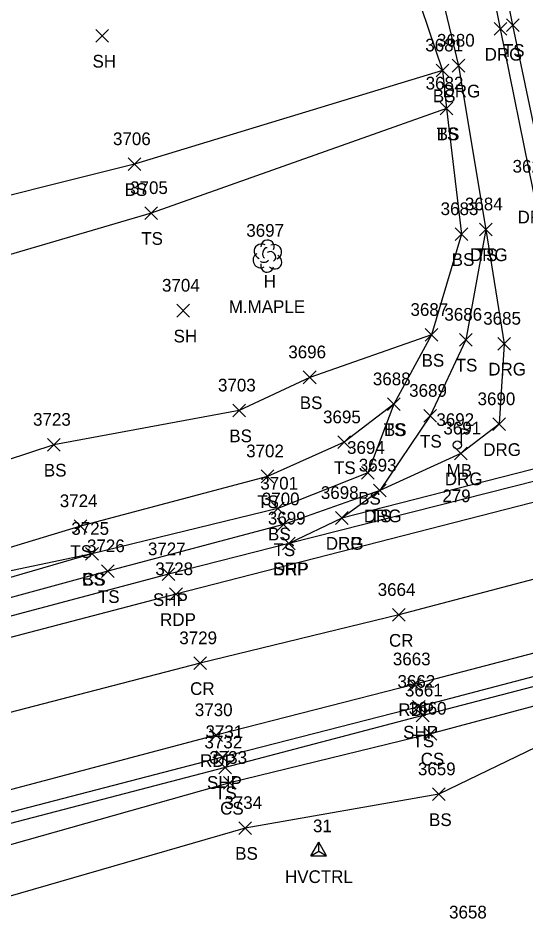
# Model space of a CAD drawing. Extents: x 1520648 to 1523413, y 732854 to 735518.
# Drawn here: x 1521334.6 to 1521414.7, y 733533.8 to 733676.1 of the extents above; entities that cross this region are included whole.
import ezdxf

# ---------------------------------------------------------------- set-up
doc = ezdxf.new("R2010")
doc.units = 0
for name, color, linetype in [('C_A', 7, 'Continuous'), ('C_I', 7, 'Continuous'), ('CPSM', 7, 'Continuous'), ('L_A', 7, 'Continuous'), ('L_C', 7, 'Continuous'), ('L_I', 7, 'Continuous'), ('L_TIC', 7, 'Continuous'), ('LELB', 7, 'Continuous'), ('LMB', 7, 'Continuous'), ('LTD', 7, 'Continuous'), ('P_A', 7, 'Continuous'), ('P_I', 7, 'Continuous'), ('P_TIC', 7, 'Continuous'), ('PET', 7, 'Continuous'), ('PRC', 7, 'Continuous'), ('PSP', 7, 'Continuous'), ('R_A', 7, 'Continuous'), ('R_I', 7, 'Continuous'), ('R_TIC', 7, 'Continuous'), ('RDG', 7, 'Continuous'), ('RDP', 7, 'Continuous')]:
    doc.layers.add(name, color=color, linetype=linetype)

msp = doc.modelspace()

# ---------------------------------------------------------------- linework, layer by layer
at = {"layer": 'CPSM'}
for p, q in [((1521380.75, 733544.19), (1521382, 733546.35)), ((1521383.25, 733544.19), (1521382, 733546.35)), ((1521382, 733544.91), (1521382, 733546.35)), ((1521380.75, 733544.19), (1521382, 733544.91)), ((1521382, 733544.91), (1521382, 733544.91)), ((1521382, 733544.91), (1521383.25, 733544.19)), ((1521380.75, 733544.19), (1521383.25, 733544.19))]:
    msp.add_line(p, q, dxfattribs=at)
at = {"layer": 'L_TIC'}
for points in [[(1521411.62, 733674.01), (1521413.62, 733676.01)], [(1521413.62, 733674.01), (1521411.62, 733676.01)], [(1521346.86, 733672.32), (1521348.86, 733674.32)], [(1521348.86, 733672.32), (1521346.86, 733674.32)], [(1521400.54, 733666.87), (1521402.54, 733668.87)], [(1521402.54, 733666.87), (1521400.54, 733668.87)], [(1521400.54, 733666.87), (1521402.54, 733668.87)], [(1521402.54, 733666.87), (1521400.54, 733668.87)], [(1521401.17, 733660.87), (1521403.17, 733662.87)], [(1521403.17, 733660.87), (1521401.17, 733662.87)], [(1521401.17, 733660.87), (1521403.17, 733662.87)], [(1521403.17, 733660.87), (1521401.17, 733662.87)], [(1521351.97, 733652.11), (1521353.97, 733654.11)], [(1521353.97, 733652.11), (1521351.97, 733654.11)], [(1521354.62, 733644.41), (1521356.62, 733646.41)], [(1521356.62, 733644.41), (1521354.62, 733646.41)], [(1521403.53, 733641.09), (1521405.53, 733643.09)], [(1521405.53, 733641.09), (1521403.53, 733643.09)], [(1521407.35, 733641.84), (1521409.35, 733643.84)], [(1521409.35, 733641.84), (1521407.35, 733643.84)], [(1521359.64, 733629.04), (1521361.64, 733631.04)], [(1521361.64, 733629.04), (1521359.64, 733631.04)], [(1521398.77, 733625.22), (1521400.77, 733627.22)], [(1521400.77, 733625.22), (1521398.77, 733627.22)], [(1521398.77, 733625.22), (1521400.77, 733627.22)], [(1521400.77, 733625.22), (1521398.77, 733627.22)], [(1521404.18, 733624.46), (1521406.18, 733626.46)], [(1521406.18, 733624.46), (1521404.18, 733626.46)], [(1521379.58, 733618.54), (1521381.58, 733620.54)], [(1521381.58, 733618.54), (1521379.58, 733620.54)], [(1521392.85, 733614.3), (1521394.85, 733616.3)], [(1521394.85, 733614.3), (1521392.85, 733616.3)], [(1521392.85, 733614.3), (1521394.85, 733616.3)], [(1521394.85, 733614.3), (1521392.85, 733616.3)], [(1521368.47, 733613.32), (1521370.47, 733615.32)], [(1521370.47, 733613.32), (1521368.47, 733615.32)], [(1521398.57, 733612.48), (1521400.57, 733614.48)], [(1521400.57, 733612.48), (1521398.57, 733614.48)], [(1521339.24, 733607.92), (1521341.24, 733609.92)], [(1521341.24, 733607.92), (1521339.24, 733609.92)], [(1521385, 733608.31), (1521387, 733610.31)], [(1521387, 733608.31), (1521385, 733610.31)], [(1521372.91, 733602.95), (1521374.91, 733604.95)], [(1521374.91, 733602.95), (1521372.91, 733604.95)], [(1521388.77, 733603.49), (1521390.77, 733605.49)], [(1521390.77, 733603.49), (1521388.77, 733605.49)], [(1521390.63, 733600.72), (1521392.63, 733602.72)], [(1521392.63, 733600.72), (1521390.63, 733602.72)], [(1521374.57, 733597.87), (1521376.57, 733599.87)], [(1521376.57, 733597.87), (1521374.57, 733599.87)], [(1521343.45, 733595.1), (1521345.45, 733597.1)], [(1521345.45, 733595.1), (1521343.45, 733597.1)], [(1521375.47, 733595.39), (1521377.47, 733597.39)], [(1521377.47, 733595.39), (1521375.47, 733597.39)], [(1521345.27, 733590.74), (1521347.27, 733592.74)], [(1521347.27, 733590.74), (1521345.27, 733592.74)], [(1521345.27, 733590.74), (1521347.27, 733592.74)], [(1521347.27, 733590.74), (1521345.27, 733592.74)], [(1521347.79, 733588.01), (1521349.79, 733590.01)], [(1521349.79, 733588.01), (1521347.79, 733590.01)], [(1521397.39, 733565.29), (1521399.39, 733567.29)], [(1521399.39, 733565.29), (1521397.39, 733567.29)], [(1521398.64, 733562.42), (1521400.64, 733564.42)], [(1521400.64, 733562.42), (1521398.64, 733564.42)], [(1521366.26, 733557.11), (1521368.26, 733559.11)], [(1521368.26, 733557.11), (1521366.26, 733559.11)], [(1521367.02, 733554.68), (1521369.02, 733556.68)], [(1521369.02, 733554.68), (1521367.02, 733556.68)], [(1521399.95, 733552.88), (1521401.95, 733554.88)], [(1521401.95, 733552.88), (1521399.95, 733554.88)], [(1521369.39, 733547.57), (1521371.39, 733549.57)], [(1521371.39, 733547.57), (1521369.39, 733549.57)]]:
    msp.add_lwpolyline(points, dxfattribs=at)
at = {"layer": 'LELB'}
for points in [[(1521685.16, 733676.19), (1521649.35, 733666.1), (1521610.03, 733655.91), (1521560.37, 733642.72), (1521505.12, 733628.18), (1521444.07, 733615.08), (1521437.41, 733615.5), (1521435.25, 733618.63), (1521426.81, 733622.91), (1521422.63, 733630.43), (1521418.08, 733649.02), (1521412.62, 733675.01), (1521409.22, 733691.67), (1521405.08, 733717.72)], [(1521391.43, 733715.08), (1521395.91, 733684.5), (1521401.54, 733667.87), (1521402.17, 733661.87), (1521404.53, 733642.09), (1521399.77, 733626.22), (1521393.85, 733615.3), (1521389.77, 733604.49), (1521375.57, 733598.87), (1521346.27, 733591.74), (1521295.03, 733576.88), (1521253.17, 733566.96), (1521225.68, 733561.04), (1521193.61, 733550.49), (1521146.45, 733540.58), (1521095.03, 733527.62), (1521049.04, 733515.84), (1521035.57, 733513.93), (1521028.78, 733520.1), (1521023.54, 733528.05)], [(1521886.12, 733515.05), (1521875.14, 733547.35), (1521860.86, 733585.06), (1521846.49, 733620.57), (1521828.87, 733649.15), (1521812.54, 733668.86), (1521809.11, 733672.39), (1521801.66, 733672.79), (1521790.92, 733669.52), (1521765.55, 733662.98), (1521730.32, 733653.15), (1521692.67, 733643.18), (1521658.49, 733634.29), (1521618.74, 733624.02), (1521569.84, 733609.89), (1521513.97, 733596.01), (1521446.41, 733578.79), (1521398.39, 733566.29), (1521367.26, 733558.11), (1521307.77, 733542.6)], [(1521879.84, 733511.18), (1521868.37, 733545.03), (1521852.96, 733582.16), (1521839.72, 733617.96), (1521822.84, 733645.34), (1521811.24, 733661.87), (1521806.64, 733667.18), (1521807.84, 733668.63), (1521807.72, 733669.91), (1521803.6, 733669.51), (1521796.92, 733667.03), (1521791.88, 733664.56), (1521768.96, 733651.98), (1521733.27, 733640.42), (1521696.36, 733629.32), (1521662.08, 733622), (1521619.41, 733620.27), (1521570.74, 733608.28), (1521513.84, 733593.12), (1521446.76, 733575.98), (1521400.95, 733553.88), (1521370.39, 733548.57), (1521314.23, 733532.31)], [(1521401.54, 733667.87), (1521352.97, 733653.11), (1521287.46, 733636.73), (1521265.62, 733611.8), (1521261.52, 733586.86)], [(1521402.17, 733661.87), (1521355.62, 733645.41), (1521298.12, 733628.54), (1521281.94, 733599.74), (1521261.52, 733586.86)], [(1521408.35, 733642.84), (1521405.18, 733625.46), (1521399.57, 733613.48), (1521391.63, 733601.72), (1521376.47, 733596.39), (1521348.79, 733589.01), (1521295.73, 733574.6), (1521253.19, 733562.87), (1521227.3, 733556.06), (1521194.61, 733547.59), (1521147.2, 733535.61), (1521095.64, 733522.47), (1521051.1, 733511.97), (1521036.15, 733508.39), (1521030.07, 733511.16), (1521025.66, 733517.9), (1521023.54, 733528.05), (1521020.72, 733532.96)], [(1521399.77, 733626.22), (1521380.58, 733619.54), (1521369.47, 733614.32), (1521340.24, 733608.92), (1521290.49, 733592.57), (1521261.52, 733586.86), (1521251.75, 733576.61), (1521246.79, 733575.04), (1521223.74, 733567.11), (1521190.26, 733560.78), (1521150.76, 733551.63), (1521094.3, 733531.11), (1521048.48, 733523.17)], [(1521393.85, 733615.3), (1521386, 733609.31), (1521373.91, 733603.95), (1521344.45, 733596.1), (1521293.71, 733580.75)], [(1521346.27, 733591.74), (1521293.71, 733580.75), (1521253.17, 733566.96)], [(1521446.76, 733575.98), (1521399.64, 733563.42), (1521368.02, 733555.68), (1521310.83, 733539.58), (1521307.98, 733540.2), (1521245.46, 733523.72), (1521206.2, 733513.3), (1521154.14, 733500.83), (1521129.34, 733494.19)]]:
    msp.add_lwpolyline(points, dxfattribs=at)
at = {"layer": 'LMB'}
for p, q in [((1521404.51, 733611.48), (1521405.8, 733611.1)), ((1521404.52, 733608.89), (1521404.51, 733611.48)), ((1521404.51, 733610.58), (1521405.8, 733611.09)), ((1521403.86, 733608.88), (1521403.86, 733608.88))]:
    msp.add_line(p, q, dxfattribs=at)
msp.add_circle((1521403.86, 733608.88), 0.656, dxfattribs=at)
at = {"layer": 'LTD'}
msp.add_line((1521373.9, 733638.68), (1521373.9, 733638.68), dxfattribs=at)
msp.add_line((1521373.9, 733638.68), (1521373.9, 733638.68), dxfattribs=at)
msp.add_arc((1521373.94, 733640.11), 1.05, 335.5272, 180.9563, dxfattribs=at)
for centre, major_axis, ratio, start_param, end_param in [((1521373.1, 733639.34), (1.21, -0.51), 0.895232, 1.570796, 4.712389), ((1521373.69, 733639.13), (-0.208, -0.792), 0.645439, 3.141593, 6.283185), ((1521374.94, 733639.26), (-1.14, -0.48), 0.949671, 1.570796, 4.712389), ((1521372.81, 733637.97), (0.58, -1.04), 0.959034, 3.141593, 6.283185), ((1521374.4, 733638.51), (-0.5, 0.667), 0.989748, 3.141593, 6.283185), ((1521374.9, 733637.84), (-1.09, 0.79), 0.841452, 1.570796, 4.712389), ((1521373.9, 733637.18), (0.26, 1.06), 0.942809, 1.570796, 4.712389), ((1521373.44, 733637.93), (-0.625, -0.083), 0.423636, 0, 3.141593)]:
    msp.add_ellipse(centre, major_axis=major_axis, ratio=ratio, start_param=start_param, end_param=end_param, dxfattribs=at)
at = {"layer": 'P_TIC'}
for points in [[(1521376.31, 733592.37), (1521378.31, 733594.37)], [(1521378.31, 733592.37), (1521376.31, 733594.37)], [(1521357.34, 733587.53), (1521359.34, 733589.53)], [(1521359.34, 733587.53), (1521357.34, 733589.53)], [(1521358.51, 733584.39), (1521360.51, 733586.39)], [(1521360.51, 733584.39), (1521358.51, 733586.39)], [(1521393.65, 733581.12), (1521395.65, 733583.12)], [(1521395.65, 733581.12), (1521393.65, 733583.12)], [(1521362.3, 733573.52), (1521364.3, 733575.52)], [(1521364.3, 733573.52), (1521362.3, 733575.52)], [(1521396.05, 733570.19), (1521398.05, 733572.19)], [(1521398.05, 733570.19), (1521396.05, 733572.19)], [(1521396.77, 733566.66), (1521398.77, 733568.66)], [(1521398.77, 733566.66), (1521396.77, 733568.66)], [(1521364.83, 733562.19), (1521366.83, 733564.19)], [(1521366.83, 733562.19), (1521364.83, 733564.19)], [(1521365.85, 733558.74), (1521367.85, 733560.74)], [(1521367.85, 733558.74), (1521365.85, 733560.74)]]:
    msp.add_lwpolyline(points, dxfattribs=at)
at = {"layer": 'PET'}
for points in [[(1521738.04, 733684.33), (1521683.5, 733669.74), (1521650.63, 733660.94), (1521611.66, 733650.62), (1521561.93, 733638.03), (1521506.75, 733623.4), (1521441.41, 733606.41), (1521359.51, 733585.39), (1521298.08, 733569.34)], [(1521729.46, 733658.42), (1521691.16, 733648.14), (1521656.53, 733638.84), (1521617.41, 733628.38), (1521568.35, 733615.73), (1521513, 733601.18), (1521444.83, 733583.68), (1521397.05, 733571.19), (1521365.83, 733563.19), (1521305.64, 733547.24)]]:
    msp.add_lwpolyline(points, dxfattribs=at)
at = {"layer": 'PRC'}
msp.add_lwpolyline([(1521726.09, 733669.37), (1521688.17, 733658.56), (1521653.92, 733649.44), (1521614.5, 733638.83), (1521565.47, 733626.81), (1521509.77, 733612.04), (1521443.86, 733595.11), (1521394.65, 733582.12), (1521363.3, 733574.52), (1521301.52, 733558.53)], dxfattribs=at)
at = {"layer": 'PSP'}
for points in [[(1521736.06, 733688.52), (1521682.58, 733672.91), (1521649.96, 733663.85), (1521610.58, 733653.51), (1521560.99, 733640.75), (1521505.9, 733626.2), (1521443.88, 733610.24), (1521377.31, 733593.37), (1521358.34, 733588.53), (1521296.5, 733572.12)], [(1521803.81, 733674.87), (1521790.84, 733671.78), (1521765.17, 733664.41), (1521730.05, 733655.17), (1521692.36, 733644.77), (1521657.88, 733635.55), (1521618.43, 733624.98), (1521569.22, 733612.2), (1521513.6, 733597.91), (1521446.12, 733580.35), (1521397.77, 733567.66), (1521366.85, 733559.74), (1521307.16, 733544.25)]]:
    msp.add_lwpolyline(points, dxfattribs=at)
at = {"layer": 'R_TIC'}
for points in [[(1521409.67, 733673.42), (1521411.67, 733675.42)], [(1521411.67, 733673.42), (1521409.67, 733675.42)], [(1521403.03, 733667.62), (1521405.03, 733669.62)], [(1521405.03, 733667.62), (1521403.03, 733669.62)], [(1521407.35, 733641.84), (1521409.35, 733643.84)], [(1521409.35, 733641.84), (1521407.35, 733643.84)], [(1521410.24, 733623.83), (1521412.24, 733625.83)], [(1521412.24, 733623.83), (1521410.24, 733625.83)], [(1521409.44, 733611.16), (1521411.44, 733613.16)], [(1521411.44, 733611.16), (1521409.44, 733613.16)], [(1521403.4, 733606.55), (1521405.4, 733608.55)], [(1521405.4, 733606.55), (1521403.4, 733608.55)], [(1521390.63, 733600.72), (1521392.63, 733602.72)], [(1521392.63, 733600.72), (1521390.63, 733602.72)], [(1521384.65, 733596.39), (1521386.65, 733598.39)], [(1521386.65, 733596.39), (1521384.65, 733598.39)], [(1521384.65, 733596.39), (1521386.65, 733598.39)], [(1521386.65, 733596.39), (1521384.65, 733598.39)], [(1521376.31, 733592.37), (1521378.31, 733594.37)], [(1521378.31, 733592.37), (1521376.31, 733594.37)]]:
    msp.add_lwpolyline(points, dxfattribs=at)
at = {"layer": 'RDG'}
for points in [[(1521395.45, 733716.63), (1521400.2, 733684.68), (1521404.03, 733668.62), (1521408.35, 733642.84), (1521411.24, 733624.83), (1521410.44, 733612.16), (1521404.4, 733607.55), (1521391.63, 733601.72), (1521385.65, 733597.39)], [(1521435.97, 733610.22), (1521429.03, 733615.22), (1521422.83, 733621.99), (1521420.09, 733628.28), (1521415.86, 733648.78), (1521410.67, 733674.42), (1521407.27, 733691.15), (1521403.1, 733717.52)]]:
    msp.add_lwpolyline(points, dxfattribs=at)
at = {"layer": 'RDP'}
msp.add_lwpolyline([(1521443.88, 733610.24), (1521435.97, 733610.22), (1521385.65, 733597.39), (1521377.31, 733593.37)], dxfattribs=at)

# ---------------------------------------------------------------- texts
at = {"layer": 'C_A'}
msp.add_text('HVCTRL', height=2, dxfattribs=at).set_placement((1521376.69, 733539.91))
at = {"layer": 'C_I'}
msp.add_text('31', height=2, dxfattribs=at).set_placement((1521381.1, 733547.91))
at = {"layer": 'L_A'}
for s, p in [('TS', (1521411.03, 733670.01)), ('SH', (1521346.35, 733668.32)), ('BS', (1521399.99, 733662.87)), ('BS', (1521399.99, 733662.87)), ('TS', (1521400.58, 733656.87)), ('BS', (1521400.61, 733656.87)), ('BS', (1521351.41, 733648.11)), ('TS', (1521354.03, 733640.41)), ('TS', (1521406.76, 733637.84)), ('BS', (1521402.97, 733637.09)), ('H', (1521373.33, 733633.68)), ('SH', (1521359.13, 733625.04)), ('BS', (1521398.22, 733621.22)), ('BS', (1521398.22, 733621.22)), ('TS', (1521403.59, 733620.46)), ('BS', (1521379.02, 733614.54)), ('BS', (1521367.91, 733609.32)), ('TS', (1521392.26, 733610.3)), ('BS', (1521392.29, 733610.3)), ('TS', (1521397.98, 733608.48)), ('BS', (1521338.68, 733603.92)), ('TS', (1521384.41, 733604.31)), ('MB', (1521402.17, 733603.88)), ('BS', (1521388.22, 733599.49)), ('TS', (1521372.32, 733598.95)), ('TS', (1521390.04, 733596.72)), ('BS', (1521374.01, 733593.87)), ('TS', (1521342.86, 733591.1)), ('TS', (1521374.88, 733591.39)), ('CS', (1521344.71, 733586.74)), ('BS', (1521344.71, 733586.74)), ('TS', (1521347.2, 733584.01)), ('TS', (1521396.8, 733561.29)), ('CS', (1521398.08, 733558.42)), ('TS', (1521365.66, 733553.11)), ('CS', (1521366.46, 733550.68)), ('BS', (1521399.4, 733548.88)), ('BS', (1521368.84, 733543.57))]:
    msp.add_text(s, height=2, dxfattribs=at).set_placement(p)
at = {"layer": 'L_C'}
for s, p in [('M.MAPLE', (1521367.83, 733629.68)), ('279', (1521401.49, 733599.88))]:
    msp.add_text(s, height=2, dxfattribs=at).set_placement(p)
at = {"layer": 'L_I'}
for s, p in [('3681', (1521398.8, 733670.87)), ('3681', (1521398.8, 733670.87)), ('3682', (1521398.86, 733664.87)), ('3682', (1521398.86, 733664.87)), ('3706', (1521349.58, 733656.11)), ('3705', (1521352.28, 733648.41)), ('3683', (1521401.22, 733645.09)), ('3684', (1521405.05, 733645.84)), ('3697', (1521370.59, 733641.68)), ('3704', (1521357.3, 733633.04)), ('3687', (1521396.47, 733629.22)), ('3687', (1521396.47, 733629.22)), ('3686', (1521401.81, 733628.46)), ('3696', (1521377.21, 733622.54)), ('3688', (1521390.54, 733618.3)), ('3688', (1521390.54, 733618.3)), ('3703', (1521366.13, 733617.32)), ('3689', (1521396.26, 733616.48)), ('3695', (1521382.69, 733612.31)), ('3723', (1521336.98, 733611.92)), ('3692', (1521400.55, 733611.88)), ('3702', (1521370.57, 733606.95)), ('3694', (1521386.47, 733607.49)), ('3693', (1521388.32, 733604.72)), ('3701', (1521372.8, 733601.87)), ('3700', (1521373.04, 733599.39)), ('3724', (1521341.19, 733599.1)), ('3725', (1521343.01, 733594.74)), ('3725', (1521343.01, 733594.74)), ('3726', (1521345.48, 733592.01)), ('3661', (1521395.6, 733569.29)), ('3660', (1521396.2, 733566.42)), ('3732', (1521364, 733561.11)), ('3733', (1521364.76, 733558.68)), ('3659', (1521397.64, 733556.88)), ('3734', (1521367.13, 733551.57)), ('3658', (1521402.55, 733534.33))]:
    msp.add_text(s, height=2, dxfattribs=at).set_placement(p)
at = {"layer": 'P_A'}
for s, p in [('SHP', (1521374.84, 733588.37)), ('SHP', (1521355.88, 733583.53)), ('RDP', (1521357, 733580.39)), ('CR', (1521393.08, 733577.12)), ('CR', (1521361.73, 733569.52)), ('RDP', (1521394.54, 733566.19)), ('SHP', (1521395.31, 733562.66)), ('RDP', (1521363.31, 733558.19)), ('SHP', (1521364.39, 733554.74))]:
    msp.add_text(s, height=2, dxfattribs=at).set_placement(p)
at = {"layer": 'P_I'}
for s, p in [('3699', (1521373.99, 733596.37)), ('3727', (1521355.08, 733591.53)), ('3728', (1521356.25, 733588.39)), ('3664', (1521391.3, 733585.12)), ('3729', (1521360.03, 733577.52)), ('3663', (1521393.69, 733574.19)), ('3662', (1521394.42, 733570.66)), ('3730', (1521362.48, 733566.19)), ('3731', (1521364.16, 733562.74))]:
    msp.add_text(s, height=2, dxfattribs=at).set_placement(p)
at = {"layer": 'R_A'}
for s, p in [('DRG', (1521408.16, 733669.42)), ('DRG', (1521401.52, 733663.62)), ('DRG', (1521413.35, 733643.78)), ('DRG', (1521405.84, 733637.84)), ('DRG', (1521408.73, 733619.83)), ('DRG', (1521407.93, 733607.16)), ('DRG', (1521401.88, 733602.55)), ('DRG', (1521389.12, 733596.72)), ('DRG', (1521383.13, 733592.39)), ('DRP', (1521383.13, 733592.39)), ('DRP', (1521374.79, 733588.37))]:
    msp.add_text(s, height=2, dxfattribs=at).set_placement(p)
at = {"layer": 'R_I'}
for s, p in [('3680', (1521400.64, 733671.62)), ('3622', (1521412.56, 733651.78)), ('3684', (1521405.05, 733645.84)), ('3685', (1521407.93, 733627.83)), ('3690', (1521407.04, 733615.16)), ('3691', (1521401.66, 733610.55)), ('3693', (1521388.32, 733604.72)), ('3698', (1521382.34, 733600.39)), ('3698', (1521382.34, 733600.39)), ('3699', (1521373.99, 733596.37))]:
    msp.add_text(s, height=2, dxfattribs=at).set_placement(p)

doc.saveas('drawing.dxf')
